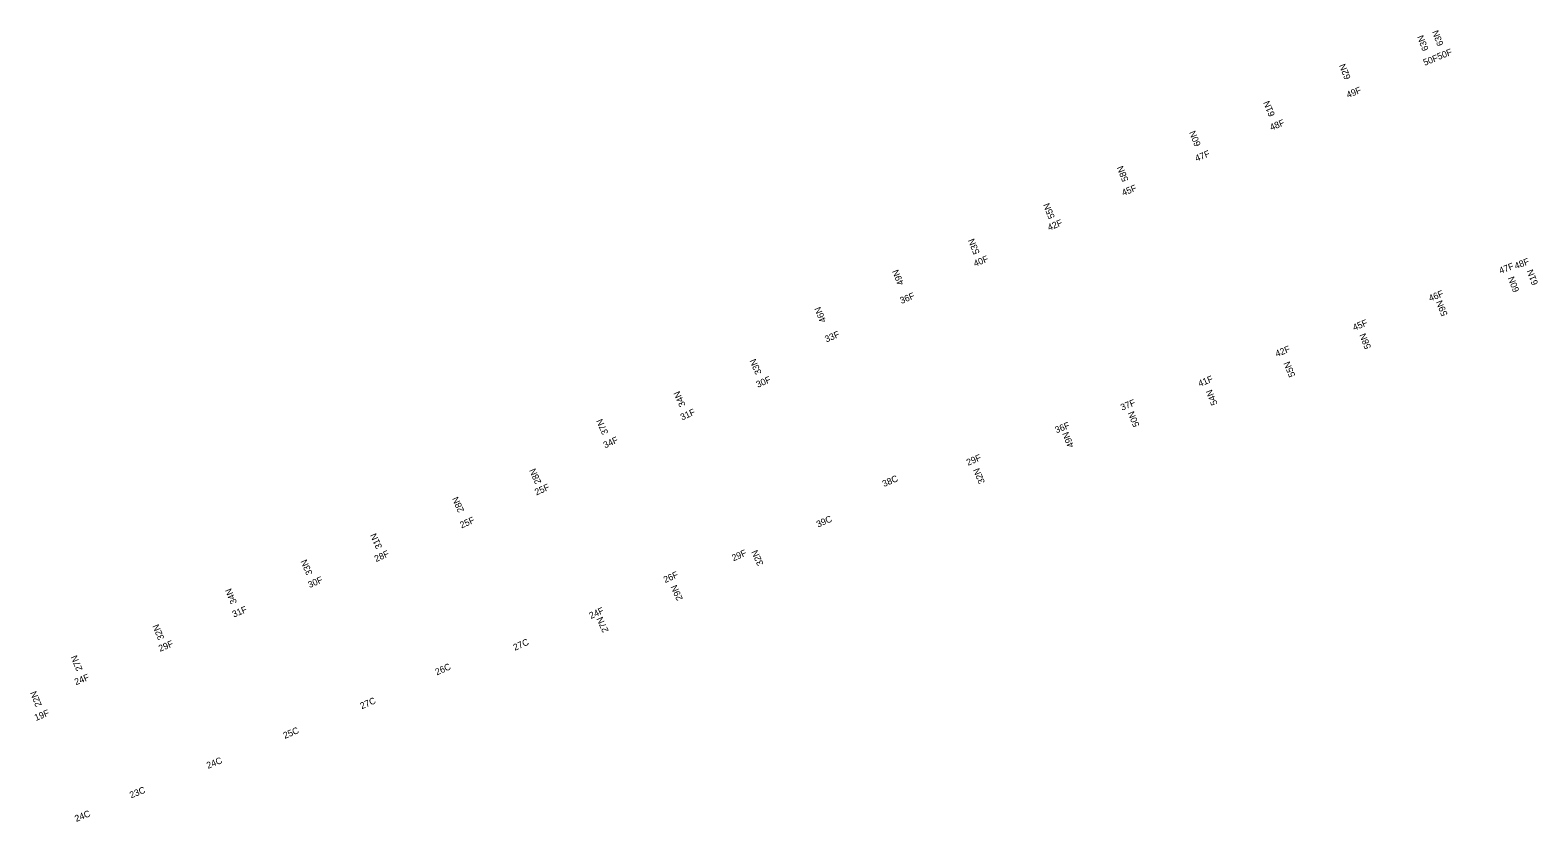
# Model space of a CAD drawing. Extents: x 1966765 to 1969235, y 1117417 to 1118004.
# Drawn here: x 1966765 to 1967686, y 1117417 to 1117900 of the extents above; entities that cross this region are included whole.
import ezdxf

# ---------------------------------------------------------------- set-up
doc = ezdxf.new("R2010")
doc.units = 0
doc.layers.add('RD_PD_TX_CstnLmt', color=7, linetype='Continuous')
doc.layers.add('RD_TX_Drainage', color=7, linetype='Continuous')

msp = doc.modelspace()

# ---------------------------------------------------------------- texts
at = {"layer": 'RD_PD_TX_CstnLmt'}
for s, rotation, p in [('50F', 20.98741, (1967616.95, 1117878.55)), ('50F', 20.74242, (1967625.49, 1117882.19)), ('49F', 21.99584, (1967570.09, 1117858.79)), ('48F', 21.99584, (1967523.27, 1117838.92)), ('47F', 21.99584, (1967477.6, 1117819.97)), ('45F', 21.99584, (1967432.79, 1117798.98)), ('42F', 21.99584, (1967387.43, 1117777.75)), ('40F', 22.00058, (1967342.19, 1117755.7)), ('47F', 20.98741, (1967663.3, 1117751.37)), ('48F', 20.74242, (1967672.7, 1117754.26)), ('36F', 22.50058, (1967297.21, 1117733.06)), ('46F', 21.99584, (1967620.36, 1117734.47)), ('45F', 21.99584, (1967573.93, 1117716.64)), ('33F', 23.00058, (1967251.34, 1117709.49)), ('42F', 21.99584, (1967526.62, 1117700.58)), ('30F', 23.50058, (1967209.41, 1117681.79)), ('41F', 21.99584, (1967479.49, 1117682.33)), ('37F', 21.99584, (1967432.03, 1117667.82)), ('31F', 24.00015, (1967163.16, 1117661.87)), ('36F', 22.00058, (1967391.95, 1117653.98)), ('34F', 24.00015, (1967116.04, 1117644.79)), ('29F', 22.50058, (1967337.86, 1117634.18)), ('38C', 23.00058, (1967286.5, 1117621.15)), ('25F', 24.00015, (1967074.12, 1117616.01)), ('25F', 24.00015, (1967028.36, 1117595.86)), ('39C', 23.50058, (1967246.24, 1117596.39)), ('28F', 23.99808, (1966976.14, 1117575.32)), ('29F', 24.00015, (1967194.55, 1117575.78)), ('30F', 23.49808, (1966935.5, 1117559.43)), ('26F', 24.00015, (1967152.8, 1117562.49)), ('31F', 22.99808, (1966889.21, 1117541.4)), ('24F', 24.00015, (1967107.41, 1117540.54)), ('29F', 22.49808, (1966844.14, 1117520.5)), ('27C', 24.00015, (1967060.98, 1117521.11)), ('24F', 21.99808, (1966792.71, 1117500.06)), ('26C', 23.99808, (1967013.29, 1117506.08)), ('27C', 23.49808, (1966967.38, 1117485.37)), ('19F', 21.9959, (1966768.26, 1117478.24)), ('25C', 22.99808, (1966920.37, 1117467.26)), ('24C', 22.49808, (1966873.45, 1117448.97)), ('23C', 21.99808, (1966826.45, 1117430.94)), ('24C', 21.9959, (1966792.88, 1117416.52))]:
    msp.add_text(s, height=4, rotation=rotation, dxfattribs=at).set_placement(p)
at = {"layer": 'RD_TX_Drainage'}
for s, rotation, p in [('63N', 110.98742, (1967619.47, 1117888.57)), ('63N', 110.66369, (1967628.59, 1117891.6)), ('62N', 111.99584, (1967571.88, 1117871.17)), ('61N', 111.99584, (1967525.58, 1117848.54)), ('60N', 111.99584, (1967480.27, 1117830.27)), ('58N', 111.99584, (1967436.07, 1117808.79)), ('55N', 111.99584, (1967391.04, 1117786.05)), ('53N', 112.00058, (1967345.12, 1117764.34)), ('49N', 112.50058, (1967298.84, 1117745.45)), ('60N', 110.98742, (1967674.93, 1117741.17)), ('61N', 110.56106, (1967686.4, 1117745.44)), ('46N', 113.00058, (1967251.35, 1117722.68)), ('59N', 111.99584, (1967631.11, 1117726.64)), ('58N', 111.99584, (1967584.32, 1117706.5)), ('33N', 113.50058, (1967211.86, 1117690.96)), ('55N', 111.99584, (1967538.01, 1117689.28)), ('34N', 114.00015, (1967165.39, 1117671.23)), ('54N', 111.99584, (1967490.48, 1117672.06)), ('37N', 114.00015, (1967118.18, 1117654.28)), ('50N', 111.99584, (1967442.78, 1117658.85)), ('49N', 112.00058, (1967402.74, 1117646.24)), ('28N', 114.00015, (1967077.24, 1117624.04)), ('32N', 112.50058, (1967348.31, 1117624.13)), ('28N', 114.00015, (1967030.06, 1117606.74)), ('31N', 113.99808, (1966979.98, 1117584.45)), ('32N', 114.00015, (1967213, 1117574.22)), ('33N', 113.49808, (1966937.45, 1117568.38)), ('29N', 114.00015, (1967163.68, 1117552.87)), ('34N', 112.99808, (1966891.21, 1117550.63)), ('32N', 112.49808, (1966846.81, 1117528.73)), ('27N', 114.00015, (1967118.34, 1117533.35)), ('27N', 111.99808, (1966796.84, 1117509.74)), ('22N', 111.9959, (1966771.93, 1117487.87))]:
    msp.add_text(s, height=4, rotation=rotation, dxfattribs=at).set_placement(p)

doc.saveas('drawing.dxf')
